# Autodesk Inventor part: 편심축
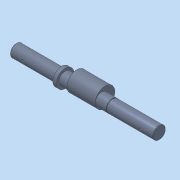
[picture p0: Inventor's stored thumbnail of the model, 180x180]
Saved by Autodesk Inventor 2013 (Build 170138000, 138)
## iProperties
Manager: 한국ATC센터
Company: 한국ATC센터
Created: 2014-10
Part Number: 편심축
Document SubType Name: Modeling
Designer: 한국ATC센터
Density: 7.86 g/cm^3
Material: 강, 연강
Mass: 1420.77 g
Surface Area: 286.549 cm^2
Volume: 180.76 cm^3
Author: KYOUNG IL JANG
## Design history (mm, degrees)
sketch "스케치1"
  geometry: L1 (-142, 0)-(142, 0); L2 (-142, 0)-(-142, 12.5); L3 (-142, 12.5)-(-52, 12.5); L4 (-52, 12.5)-(-52, 17.5); L5 (-52, 17.5)-(-45, 17.5); L6 (-45, 17.5)-(-45, 12.5); L7 (-45, 12.5)-(48.65, 12.5); L8 (48.65, 12.5)-(48.65, 11.95); L9 (48.65, 11.95)-(50, 11.95); L10 (50, 11.95)-(50, 12.5); L11 (50, 12.5)-(142, 12.5); L12 (142, 12.5)-(142, 0); L13 (109, 12.5)-(109, 9.1); L14 (109, 9.1)-(134, 9.1); L15 (134, 9.1)-(134, 12.5); L16 (117, -12.5)-(119.5, -12.5); L17 (119.5, -12.5)-(117, -10); L18 (117, -10)-(117, -12.5); L19 (-109, 12.5)-(-109, 9.1); L20 (-109, 9.1)-(-134, 9.1); L21 (-134, 9.1)-(-134, 12.5); L22 (-117, -12.5)-(-117, -10); L23 (-117, -10)-(-114.5, -12.5); L24 (-114.5, -12.5)-(-117, -12.5); 2 further points
  constraints: 48 end point, 11 parallel, 8 perpendicular, 5 collinear, 4 point on line, 1 coincident, 1 horizontal, 1 midpoint, 1 vertical
  dimensions: "d0" = 284 distance of L1.start L1.end (derived); "d1" = 25 diameter of L3 L1; "d2" = 35 diameter of L5 L1; "d3" = 90 distance of L2.end L3.end; "d4" = 187 distance between parallel lines of L12 L6; "d6" = 1.35 distance of L8.end L9.end; "d7" = 23.9 diameter of L9 L1; "d8" = 3.4 distance between parallel lines of L14 L11; "d9" = 8 distance between parallel lines of L15 L12; "d10" = 25 distance of L13.end L14.end; "d11" = 25 diameter of L16 L1 (= d1); "d12" = 25 distance from line of L12 L16.start; "d13" = 45 deg angle of L17 L18; "d14" = 5 diameter of L16.end L18; "d27" = 92 distance between parallel lines of L10 L12; "d32" = 7 distance of L4.end L5.end; "d33" = 8 distance between parallel lines of L2 L21; "d34" = 25 distance between parallel lines of L21 L19; "d35" = 3.4 distance between parallel lines of L3 L20; "d36" = 25 distance from line of L22.start L2; "d37" = 5 diameter of L23.end L22
revolve "회전1" stored, may be unused: angle "d15" = 90 deg
revolve "회전2" stored, may be unused: angle "d16" = 90 deg
revolve "회전3" stored, may be unused: angle "d38" = 90 deg
extrude "돌출1" cut sketch "스케치1" stored distance "d17" = 8; taper "d18" = 0 deg
fillet "모깎기1" dims "d19" = 4
node "작업 평면1"
sketch "스케치2"
  geometry: L1 (12.99, -6.5)-(8.66, -14); L2 (-12.99, -6.5)-(-8.66, -14); C1 r 12.5 at (0, 0) reference; C2 r 19.5 at (0, 7); A1 r 15 centre (0, 1) between (12.99, -6.5) and (-12.99, -6.5); A2 r 10 centre (0, -9) between (-8.66, -14) and (8.66, -14); 1 further point
  constraints: 5 tangent, 4 end point, 4 point on circle, 3 centre point, 3 vertical alignment
  dimensions: "d21" = 7 distance of point (0, 0) C2.centre; "d30" = 39 diameter of C2 (derived); "d39" = 10 distance of A2.centre A1.centre; "d40" = 30 diameter of A1; "d41" = 20 diameter of A2; "d42" = 1 distance of point (0, 0) A1.centre
extrude "돌출2" join sketch "스케치2" distance "d22" = 56; taper "d23" = 0 deg
chamfer "모따기1" distance "d24" = 1; stored, may be unused: second distance "d25" = 2, angle "d26" = 45 deg
node "솔리드1"
other parameters: "d20" = 16
